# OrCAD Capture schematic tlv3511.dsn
size A
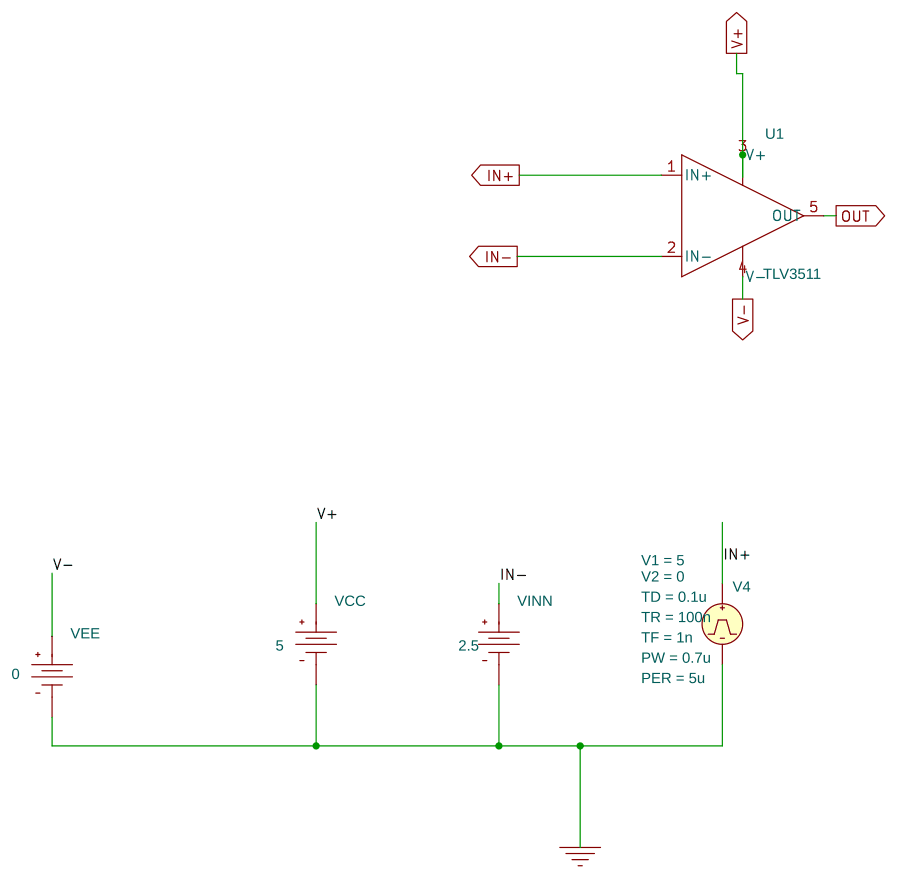
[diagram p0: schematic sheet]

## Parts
U1  TLV3511
V4  VPULSE
VCC  VDC
VEE  VDC
VINN  VDC

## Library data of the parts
U1 = TLV3511
V4 = VPULSE: PER: 5u; PW: 0.7u; TD: 0.1u; TF: 1n; TR: 100n; V1: 5; V2: 0
VCC = VDC: DC: 5
VEE = VDC: DC: 0
VINN = VDC: DC: 2.5

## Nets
0: V4.2(-) VCC.1(-) VEE.1(-) VINN.1(-)
IN+: U1.1(IN+) V4.1(+)
IN-: U1.2(IN-) VINN.0(+)
OUT: U1.5(OUT)
V+: U1.3(V+) VCC.0(+)
V-: U1.4(V-) VEE.0(+)
